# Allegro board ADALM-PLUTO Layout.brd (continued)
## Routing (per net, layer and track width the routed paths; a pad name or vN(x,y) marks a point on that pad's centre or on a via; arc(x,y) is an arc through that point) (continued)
UNNAMED_7_CAP_I147_N1: length 1.3
  TOP w0.102: C205.1 11.29,15.07 R100.1
UNNAMED_7_CAP_I149_N1: length 1.6
  BOTTOM w0.102: Y3.3 14,12.16
  BOTTOM w0.127: 14,12.16 arc(14.01,12.2) C204.1
UNNAMED_7_CNBNC3P_I43_CNTR: length 14.7
  TOP w0.127: D3.2 27.23,47.42
  TOP w0.483: T2.3 38.5,45.27 arc(38.49,45.58) 38.45,45.88 arc(38.45,45.91) 38.44,45.95 arc(38.18,46.48) 37.78,46.93 arc(37.14,47.29) 36.42,47.42 RX2A.1
UNNAMED_7_CNBNC3P_I74_CNTR: length 15.7
  TOP w0.127: D10.2 27.13,19.28
  TOP w0.483: T3.3 39.4,23.29 39.46,22.91 arc(39.07,21.57) 37.8,21 34.06,21 arc(32.36,20.78) 30.77,20.14 arc(29.18,19.49) 27.47,19.28 TX2A.1
UNNAMED_7_CNBNC3P_I125_CNTR: length 9.5
  TOP w0.102: CLK_OUT.1 7.73,10.72 arc(7.74,10.73) D8.2 7.74,14.37 arc(7.79,14.61) 7.92,14.81 arc(8.2,14.99) 8.54,15.06 R100.2 10.34,13.7 arc(10.33,13.67) R98.2
UNNAMED_7_CNBNC5P_I64_CNTR: length 17.8
  TOP w0.305: D4.2 6.32,46.41 6.3,46.39
  TOP w0.483: RX1A.1 8.73,46.39 arc(9.67,46.27) 10.55,45.9 T1.3
UNNAMED_7_CNBNC5P_I83_CNTR: length 18
  TOP w0.305: 6.3,22.95 6.28,22.96 D9.2
  TOP w0.483: TX1A.1 7.11,22.95 arc(9.44,23.91) 10.41,26.24 10.41,28.47 arc(10.75,29.88) 11.71,30.98 arc(12.25,31.28) 12.85,31.47 arc(13.16,31.52) 13.48,31.54 T5.3
UNNAMED_7_ICLTC6957V3_I120_IN: length 2.2
  TOP w0.102: U17.3 arc(18.62,12.27) R10.2
UNNAMED_7_ICLTC6957V3_I120_OUT1: length 1.9
  TOP w0.102: R86.1 12.91,12.24 arc(13.03,12.22) U17.10
UNNAMED_7_ICLTC6957V3_I120_OUT2: length 2.4
  TOP w0.102: R98.1 11.27,13.63 11.27,13.51 arc(11.31,13.27) 11.45,13.06 arc(11.75,12.85) 12.11,12.77 13,12.77 arc(13.05,12.78) 13.1,12.79 arc(13.12,12.79) U17.9
UNNAMED_7_ICLTC6957V3_I120_SD1: length 14.1
  TOP w0.305: U17.12 14.58,10.84 v1(15.29,10.13) 15.29,8.77 Q3.3 ; U17.7 13.17,14.12 R85.2 12.55,16.11 v1(12.55,16.46)
  L5_SIG w0.305: v1(15.29,10.13) 15.29,13.96 12.8,16.46 v1(12.55,16.46)
UNNAMED_7_RES_I152_N1: length 4
  BOTTOM w0.127: 12.77,6.25 12.83,6.2 R5.2
  BOTTOM w0.305: R67.1 10.55,8.22 Y3.1 12.77,7.55 12.77,6.25
UNNAMED_7_RES_I152_N2: length 5.4
  BOTTOM w0.305: R101.2 7.85,8.84 Q2.3 8.05,8.78 8.48,9.22 10.46,9.22 R67.2
UNNAMED_9_ADP198_I365_VOUT: length 5.2
  TOP w0.254: 101.2,42.75 U16.A2 101.58,42.37
  TOP w0.508: F1.1 101.59,41.83 ; F1.1 101.59,40.61 ; F1.1 101.06,41.22
  TOP w0.635: 100.18,41.16 C172.1 100.87,41.79 ; 98.21,41.79 C171.1 98.91,41.16
UNNAMED_9_ADP2114_I196_FREQ: length 1.6
  TOP w0.305: U6.3 96.09,43.52 R53.2
UNNAMED_9_ADP2114_I196_OPCFG: length 1.8
  TOP w0.305: v1(95.35,44.9) 95.23,45.02 U6.6
  BOTTOM w0.508: v1(95.35,44.9) 94.47,44.9 R54.1
UNNAMED_9_ADP2114_I196_SS1: length 2.1
  TOP w0.203: v2(93.06,40.71) 92.8,41.09 U6.30
  BOTTOM w0.254: C7.2 93.38,40.4 v2(93.06,40.71)
UNNAMED_9_ADP2114_I196_SS2: length 1.9
  TOP w0.203: v2(93.06,47.83) 92.8,47.44 U6.11
  BOTTOM w0.305: v2(93.06,47.83) 93.06,47.3 C139.2
UNNAMED_9_ADP2114_I196_SW1: length 3.7
  TOP w0.305: 88.49,42.54 88.97,43.02 U6.23 ; 89.25,41.98 89.51,42.24 89.51,42.43 U6.24 88.9,42.52
  BOTTOM w0.203: R89.1 v1(87.24,42.4)
UNNAMED_9_ADP2114_I196_SW3: length 2.1
  TOP w0.305: 89.28,46.54 89.48,46.34 89.48,46.13 U6.17 88.9,46.02 ; 88.9,45.52 U6.18
UNNAMED_9_CAP_I163_N1: length 7
  TOP w0.305: 83.84,37.67 C146.1 84.67,38.64
  TOP w0.762: 82.71,41.22 L3.2 83.7,39.13
  TOP w1.016: 83.12,37.37 L5.1 81.76,38.15
UNNAMED_9_CAP_I214_N2: length 1
  BOTTOM w0.508: R60.2 C147.2
UNNAMED_9_CAP_I224_N2: length 1
  TOP w0.305: R61.2 C144.2
UNNAMED_9_CAP_I358_N2: length 5.4
  TOP w0.305: 106.91,40.52 C177.2 ; C177.2 106.21,41.16 ; C177.2 107.61,41.16
  TOP w0.508: R55.1 105.72,30.51 106.14,30.93
  TOP w0.635: 107.69,39.61 P2.SH3 106.48,38.84
UNNAMED_9_CAP_I377_N2: length 4.5
  TOP w0.508: C181.2 104.62,48.71
  TOP w0.762: 106.48,48.27 P3.SH1 107.69,47.51 ; 106.14,47.32 R58.1 105.47,48.22
UNNAMED_9_CAP_I446_N1: length 5.4
  TOP w0.305: D2.5 102.46,53.99
  TOP w0.406: 103.65,53.75 P3.1
  TOP w0.508: 97.06,55.43 E11.2 97.91,56.41 ; 100.18,54.43 C214.1 99.32,53.63
UNNAMED_9_CAP_I447_N1: length 7.1
  TOP w0.508: 95.36,55.43 E11.1 94.51,56.41
  TOP w0.635: C213.1 92.65,53.63 ; C213.1 90.94,53.63 ; C213.1 91.79,54.43 ; E9.2 92.77,55.48 ; E9.2 91.79,54.63 ; E9.2 90.82,55.48
UNNAMED_9_CHOKE4P_I350_N2: length 7.1
  TOP w0.102: 101.95,34.49 101.59,34.86 99.49,34.86 99.23,34.6 L6.2 ; 101.95,34.49 102.32,34.86 104.13,34.86 104.24,34.74 104.94,34.74 P2.3 ; 101.95,34.49 D1.1
UNNAMED_9_CHOKE4P_I350_N3: length 7.1
  TOP w0.102: 101.95,35.51 101.95,35.51 101.57,35.13 99.51,35.13 99.23,35.4 L6.3 ; 101.95,35.51 102.34,35.13 104.11,35.13 104.24,35.25 104.95,35.25 P2.2 ; 101.95,35.51 D1.6
UNNAMED_9_CN5P3SHLD_I359_N1: length 6.4
  TOP w0.305: 101.48,37.32 E3.2 ; E3.2 D1.5 ; E3.2 103.44,37.32 ; 100.39,36.56 C211.1 101.19,37.41
  TOP w0.406: 103.81,35.97 P2.1
UNNAMED_9_CN5P3SHLD_I378_N4: length 2.2
  TOP w0.127: D2.3 102.97,52.02 103.22,51.76 104.98,51.76 P3.4
UNNAMED_9_LINLTC4415_I386_CLIM1: length 4.1
  TOP w0.127: U8.4 91.29,60.3 v1(91.28,60.29)
  BOTTOM w0.127: R78.2 91.16,61.41 91.28,61.29 v1(91.28,60.29)
UNNAMED_9_LINLTC4415_I386_CLIM2: length 5.1
  TOP w0.127: U8.5 91.79,59.91 v1(91.79,59.91)
  BOTTOM w0.127: v1(91.79,59.91) 91.79,60.65 92.56,61.41 R73.1
UNNAMED_11_741G126_I97_Y: length 3.3
  BOTTOM w0.254: U10.4 59.77,64.38 R94.2 R95.1
UNNAMED_11_CAP_I83_N1: length 5.2
  BOTTOM w0.254: U9.9 67.6,59.64 C187.1 70.24,58.05 R92.1 70.34,57.97 R80.2
UNNAMED_11_CAP_I92_N1: length 2
  BOTTOM w0.254: C189.1 69.44,59.51 68.38,60.57 U9.8
UNNAMED_11_ICFT230XQ_I103_USBDM: length 1.8
  BOTTOM w0.102: U9.7 69.41,61.22 R79.2
UNNAMED_11_ICFT230XQ_I103_USBDP: length 1.9
  BOTTOM w0.102: R81.2 69.28,61.87 U9.6
UNNAMED_11_ICUSB3320C_I29_RBIAS: length 1.6
  TOP w0.127: v1(79,28.32) U15.24
  BOTTOM w0.127: R77.1 79,27.81 v1(79,28.32)
UNNAMED_11_ICUSB3320C_I29_REFCL: length 2.2
  TOP w0.254: U15.26 77.8,29.4 R82.1
UNNAMED_11_RES_I67_N2: length 1.5
  TOP w0.305: R82.2 78.46,32.47 Y1.3
USB_FS_SLEEP: length 3.6
  BOTTOM w0.254: U10.1 62.05,61.29 R93.1 63.05,61.22 U9.14
USB_ID: length 31.8
  TOP w0.127: U15.23 80.19,26.98 81.77,28.56 v1(81.77,29.07) ; D1.3 103.25,34.02 v1(103.87,34.02) P2.4
  L5_SIG w0.127: v1(103.87,34.02) 103.11,34.78 93.2,34.78 92.44,34.02 92.44,32.5 89.65,29.7 82.41,29.7 v1(81.77,29.07)
USB_OTG_CPEN: length 41
  TOP w0.127: U15.17 79,23.33 79.36,22.97 v1(80.76,22.97) ; v1(101.7,44.52) 102.08,44.15 U16.B1
  L5_SIG w0.127: v1(101.7,44.52) 101.66,44.56 100.09,44.56 96.49,40.97 96.49,36.97 94.69,35.16 93.05,35.16 92.06,34.18 92.06,32.65 89.49,30.08 81.52,30.08 81.01,29.58 81.01,28.56 81.27,28.31 81.27,24.75 80.76,24.24 v1(80.76,22.97)
USB_OTG_N: length 26.2
  TOP w0.102: L6.4 96.39,35.4 96.11,35.13 95.58,35.13 95.24,34.78 95.24,28.23 94.4,27.39 85.58,27.39 83.06,24.86 79.42,24.86 79.31,24.98 U15.19
USB_OTG_P: length 26.1
  TOP w0.102: L6.1 96.39,34.6 96.18,34.81 95.64,34.81 95.5,34.67 95.5,28.12 94.51,27.12 85.69,27.12 83.17,24.6 79.41,24.6 79.29,24.48 U15.18
USB_UART_N: length 40.4
  TOP w0.102: P3.2 104.16,53.1 103.97,52.91 102.33,52.91 101.95,53.29 ; 101.95,53.29 D2.6 ; 101.95,53.29 101.7,53.03 101.45,53.03 v1(101.32,53.16)
  L5_SIG w0.102: v1(101.32,53.16) 100.92,53.16 100.67,52.91 97.12,52.91 94.33,55.7 85.32,55.7 81.13,59.89 74.78,59.89 73.38,61.29 73.38,61.9 v1(73.65,62.17)
  BOTTOM w0.102: R79.1 71.14,60.91 71.14,60.91 71.85,60.91 ; v1(73.65,62.17) 73.38,61.9 73.38,61.61 73.1,61.32 72.27,61.32 71.85,60.91 ; 71.85,60.91 C196.2
USB_UART_P: length 41
  TOP w0.102: 101.95,52.27 101.7,52.52 101.45,52.52 v1(101.32,52.4) ; 101.95,52.27 D2.1 ; 101.95,52.27 102.32,52.64 103.97,52.64 104.16,52.45 P3.3
  L5_SIG w0.102: v1(72.84,62.17) 73.11,61.9 73.11,61.18 74.67,59.62 81.02,59.62 85.21,55.43 94.22,55.43 97.01,52.65 100.67,52.65 100.92,52.4 v1(101.32,52.4)
  BOTTOM w0.102: C197.2 72.08,62.09 72.08,62.08 ; v1(72.84,62.17) 73.11,61.9 73.11,61.72 72.99,61.59 72.31,61.59 72.08,61.83 72.08,62.08 ; 72.08,62.08 71.85,62.3 R81.1
USB_UART_TX: length 4.7
  BOTTOM w0.254: U10.2 60.42,61.92 60.7,62.2 R107.2 62.92,61.87 U9.15
USB_VBUS_OTG: length 30.3
  TOP w0.254: v1(82.92,29.07) 80.5,26.65 79.74,26.65 79.57,26.48 U15.22
  L5_SIG w0.508: v1(82.92,29.07) 89.9,29.07 93.19,32.36 v1(93.19,33.64) v1(93.83,33.64)
  BOTTOM w0.508: R88.2 100.56,40.21 98.52,38.17 96.37,38.17 93.83,35.63 v1(93.83,33.64) v1(93.19,33.64)
USR_BTN: length 67.2
  TOP w0.127: U4.B9 59.53,32.15 63.33,32.15 63.83,31.65 68.94,31.65 70.25,30.34 70.6,30.34 70.98,30.72 70.98,31.27 71.23,31.53 73.31,31.53 75.04,33.26 75.04,35.42 77.71,38.08 v1(79.49,38.08)
  TOP w0.203: v1(105.81,22.68) S1.1
  L6_SIG w0.127: v1(79.49,38.08) 82.48,38.08 85.82,34.74 85.82,28.27 89.38,24.71 89.38,23.19 89.76,22.81 90.65,22.81 92.17,21.28 100.18,21.28 100.68,21.79 104.92,21.79 v1(105.81,22.68)
  BOTTOM w0.203: v1(79.49,38.08) 79.87,37.7 R57.2
USR_LED: length 57.8
  TOP w0.102: U4.D10 v2(57.93,31.35)
  TOP w0.127: v1(100.68,12.98) R75.1 103.15,12.98 Q4.1
  L6_SIG w0.127: v1(100.68,12.98) 90.57,12.98 85.44,18.11 85.44,22.73 78.73,29.45 78.34,29.45 76.44,31.35 74.15,31.35 72.75,29.94 70.04,29.94 69.54,30.44 68.74,30.44 67.84,31.35 67.84,31.35 59.34,31.35 58.93,30.94 58.33,30.94 v2(57.93,31.35)
VTT_0P75: length 31.4
  TOP w0.203: v1(42.63,52.97) C79.1 41.96,54.23 41.6,54.58 U14.3
  BOTTOM w0.305: 48.92,46.84 R19.2 ; R19.2 48.46,47.25 ; R19.2 49.37,47.25 ; C101.1 44.97,57.6 ; C101.1 44.41,58.16 ; C101.1 44.41,57.05 ; R35.2 52.72,57.5 ; R35.2 R39.2 ; R35.2 R16.2 ; 46.19,50.27 R18.2 ; R18.2 R27.2 ; R18.2 46.6,50.27 R29.2 ; 49.96,47.25 R28.2 ; R28.2 50.42,46.84 ; R28.2 R30.2 ; R29.2 46.19,51.07 ; R29.2 R22.2 ; 46.19,49.47 R27.2 ; R27.2 46.6,49.01 ; 46.5,53.61 R34.2 ; R34.2 R17.2 ; R34.2 46.09,54.07 ; R31.2 R37.2 51.49,53.27 ; 46.6,47.81 R20.2 ; R20.2 46.6,48.73 ; R20.2 46.19,48.27 ; R39.2 R33.2 ; R39.2 53.52,57.5 ; R33.2 54.32,57.5 ; R33.2 54.78,57.09 ; 46.09,54.88 R17.2 ; R17.2 R26.2 46.09,55.68 ; 51.22,46.84 R30.2 ; R30.2 R21.2 ; R16.2 51.92,57.5 ; R16.2 R23.2 ; 42.25,54.38 R43.1 42.81,54.94 ; R23.2 51.12,57.5 ; R23.2 R24.2 50.32,57.5 ; R22.2 46.6,52.33 ; R22.2 46.19,51.87 ; R38.2 R21.2 ; R21.2 52.02,46.84 ; 51.49,52.47 R32.2 ; 51.49,51.67 R36.2 ; R25.2 48.12,57.5
VTTVREF: length 69.4
  TOP w0.152: 52.02,51.17 v2(52.02,50.27)
  TOP w0.305: U2.M8 v2(52.02,50.27) ; 44.13,58.48 44.24,58.48 C81.1 ; 44.13,58.48 U14.6 ; 44.13,58.48 arc(44.19,58.46) 44.25,58.43 arc(44.24,58.44) 44.23,58.46 C84.1 ; U2.H1 v2(55.22,55.87) ; U4.F4 v2(56.33,36.95)
  TOP w0.508: v2(55.22,55.87) v1(55.22,58.62) 54.58,58.62 53.69,57.73 49.25,57.73 48.36,58.62 45.82,58.62 ; 45.82,58.62 44.44,58.62 44.25,58.43 ; 45.82,58.62 45.82,53.77 46.92,52.67 51.12,52.67 52.02,51.77 52.02,51.17
  BOTTOM w0.152: v2(56.33,36.95) 56.72,37.34 56.72,38.16 56.32,38.56 55.92,38.16 55.92,37.36 56.33,36.96 v2(56.33,36.95)
  BOTTOM w0.305: C102.1 52.5,49.78 v2(52.02,50.27) ; v2(55.22,55.87) 55.71,55.87 C63.2 ; 57.92,40.26 C99.2
  BOTTOM w0.508: 56.32,38.56 56.52,38.76 56.52,39.66 57.12,40.26 57.92,40.26 57.92,40.37 63.33,45.78 63.33,56.78 62.53,57.58 57.53,57.58 56.49,58.62 v1(55.22,58.62)

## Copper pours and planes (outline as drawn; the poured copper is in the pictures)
1V8 on TOP (solid shape): 38.61,10.59 38.8,10.59 38.9,10.54 39.01,10.53 39.69,10.53 39.74,10.53 39.79,10.54 39.85,10.54 39.85,10.49 39.91,10.49 39.91,10.43 39.89,10.38 39.89,10.33 39.89,9.64 39.9,9.56 39.93,9.48 39.93,9.22 41.76,9.22 41.76,8.94 41.72,8.91 41.68,8.86 41.41,8.86 41.27,8.8 41.21,8.66 41.21,8.25 41.27,8.11 41.41,8.05 41.68,8.05 41.72,8.01 41.76,7.97 41.76,6.68 39.34,6.68 37.56,8.46 37.56,11.38 38.61,11.38
1V8 on TOP: 84.94,36.52 81.13,36.52 81.13,30.68 85.44,30.68 85.44,36.01
1V8 on TOP: 40.13,55.7 40.13,54.02 40.03,53.92 34.69,53.92 34.69,56.46 38.58,56.46 39.36,55.69 40.12,55.69
1V8 on TOP: 34.64,13.03 31.34,13.03 31.34,11.5 31.85,11 31.85,9.09 34.64,9.09
1V8 on BOTTOM: 24.99,58.62 24.99,56.21 26.13,56.21 26.26,56.08 26.26,54.18 29.94,54.18 29.94,57.6 28.93,57.6 27.91,58.62
1V8 on BOTTOM: 66.27,26.87 63.6,26.87 63.6,33.09 66.27,33.09
1V8 on BOTTOM: 82.66,30.68 85.19,30.68 85.19,35.38 82.66,35.38
1V8 on L8_PWR: 48.48,63.06 52.28,59.26 56.08,63.06 56.08,68.7 66.96,68.46 77.82,67.88 77.82,56.46 44.55,56.46 43.53,57.48 43.53,60.4 37.82,60.4 37.06,59.64 37.06,56.97 37.18,56.84 39.15,56.84 39.15,51.25 40.35,50.05 84.36,50.05 84.36,16.01 98.27,16.01 98.27,5.22 59.6,5.22 59.6,11.31 54.14,11.31 54.14,13.73 50.84,13.73 50.84,11.31 47.85,11.31 42.77,6.23 31.15,6.23 31.15,14.11 36.74,14.11 36.74,23.69 43.47,30.42 43.47,41.35 34.83,49.99 34.83,54.11 26.33,54.11 26.33,56.14 31.6,56.14 31.6,67.98 40.03,68.42 48.48,68.66
1V35 on TOP: 55.73,41.96 55.73,44.17 58.32,44.17 58.32,41.96
1V35 on TOP: 81.25,45.29 81.25,52.14 80.36,53.03 80.36,55.83 84.43,55.83 84.43,45.29
1V35 on TOP: 67.54,52.78 63.73,52.78 63.73,55.32 67.54,55.32
1V35 on L3_PWR: 38.64,52.21 38.64,59.57 50.82,59.55 52.27,59.26 53.73,59.55 77.13,59.51 77.13,56.33 83.48,56.33 83.48,41.09 78.4,41.09 78.4,35.38 57.57,35.38 55.67,37.28 51.09,37.28 51.09,33.79 46.33,33.79 45.12,35 45.12,48.72 41.63,52.21
GND on TOP: 48.48,63.06 52.28,59.26 56.08,63.06 56.08,68.7 80.14,67.71 104.08,65.04 104.95,64.9 107.49,63.47 108.5,60.73 108.5,57.47 108.5,55.88 107.56,55.88 106.81,55.57 106.5,54.82 106.81,54.07 107.56,53.76 108.5,53.76 108.5,51.13 107.56,51.13 106.81,50.82 106.5,50.07 106.81,49.32 107.56,49.01 108.5,49.01 108.5,38.1 107.56,38.1 106.81,37.79 106.5,37.04 106.81,36.29 107.56,35.98 108.5,35.98 108.5,33.35 107.56,33.35 106.81,33.04 106.5,32.29 106.81,31.54 107.56,31.23 108.5,31.23 108.5,29.65 108.5,10.07 108.5,8.6 107.49,5.87 104.95,4.43 104.08,4.29 80.14,1.63 56.08,0.64 56.08,6.28 52.28,10.07 48.48,6.28 48.48,0.68 24.49,1.9 0.64,4.78 0.64,21.69 3.55,21.69 3.63,21.77 3.63,24.2 0.64,24.2 0.64,45.13 3.4,45.13 3.27,45.26 3.27,47.65 0.64,47.65 0.64,64.55 24.49,67.44 48.48,68.66 ; 15 cut-outs
GND on L3_PWR: 0.64,64.55 24.49,67.44 48.48,68.66 48.48,63.06 48.82,61.48 49.79,60.19 38.01,60.21 38.01,52.21 23.4,52.21 23.4,43.63 30.64,36.39 30.64,23.82 32.04,22.42 32.04,9.41 15.78,9.41 15.78,2.75 8.2,3.68 0.64,4.78
GND on L5_SIG: 56.08,68.7 77.28,67.91 98.4,65.83 98.4,64.21 94.59,64.21 94.59,58.8 94.28,58.8 93.93,58.44 93.93,52.45 94.03,52.35 98.4,52.35 98.4,41.09 97.13,39.82 97.13,38.86 97.13,36.33 97.13,36.33 102.21,36.33 102.53,36.01 102.53,29.35 108.48,29.35 108.48,26.92 108.5,26.92 108.5,15.52 108.5,10.08 108.5,8.6 107.49,5.87 104.95,4.43 104.08,4.29 81.55,1.74 58.9,0.67 57.49,0.65 56.08,0.64 56.08,6.28 52.28,10.07 48.48,6.28 48.48,0.68 40.48,0.9 32.48,1.3 32.48,1.3 19.89,2.32 7.34,3.8 3.99,4.28 0.64,4.78 0.64,64.55 1.7,64.72 1.7,64.72 16.68,66.68 31.72,67.98 31.72,67.98 48.48,67.98 48.48,67.13 48.48,63.06 52.28,59.26 56.08,63.06 56.08,67.13 ; 1 cut-out
GND on L8_PWR: 20.23,40.52 35.22,40.52 35.22,23.51 36.1,23.51 36.1,22.3 30.08,28.33 27.34,28.33 27.34,21.85 20.23,21.85
GND on L8_PWR: 108.5,27.38 108.5,8.61 107.49,5.87 104.95,4.43 104.08,4.29 80.14,1.63 56.08,0.64 56.08,6.28 55.56,8.2 54.14,9.59 54.14,10.68 58.96,10.68 58.96,4.58 98.33,4.58 98.33,16.65 85,16.65 85,27.38
GND on L8_PWR: 0.64,64.55 24.49,67.44 48.48,68.66 48.48,63.06 48.66,61.91 49.17,60.87 34.2,60.84 34.2,59.83 10.83,59.83 10.83,19.44 9.49,19.44 8.29,18.24 8.29,9.03 21.63,9.03 21.63,14.11 24.04,14.11 24.04,1.93 12.31,3.16 0.64,4.78
PGND on TOP: 98.4,50.11 98.52,49.98 98.52,47.44 102.46,47.44 102.72,47.19 102.72,46.3 103.22,46.3 103.22,50.75 104.87,50.75 104.87,52.4 96.24,52.4 96.11,52.27 96.11,50.11
PGND on L2_GND, L9_GND: 105.26,55.32 98.02,55.32 97.76,55.57 97.76,56.97 96.11,56.97 96.11,50.11 98.4,50.11 98.52,49.98 98.52,47.44 102.46,47.44 102.72,47.19 102.72,46.3 104.37,46.3 104.37,48.08 103.22,48.08 103.22,49.73 104.62,49.73 105.76,50.87 105.76,54.81
VCCPINT on TOP: 56.03,21.74 64.18,21.74 64.18,24.09 56.03,24.09
VCCPINT on TOP: 76.81,13.03 86.84,13.03 86.84,18.23 76.81,18.23
VCCPINT on L3_PWR: 51.73,36.65 55.4,36.65 57.31,34.74 78.4,34.74 78.4,23.95 83.79,23.95 83.79,15.06 68.55,15.06 68.55,17.92 51.09,17.92 51.09,33.16 51.73,33.16
VDD_INTERFACE on TOP: 31.98,13.66 31.98,17.22 32.1,17.35 32.1,17.97 34.64,17.97 34.64,13.66
VDD_INTERFACE on L8_PWR: 27.98,27.7 29.81,27.7 36.1,21.41 36.1,14.74 27.98,14.74
VIN on TOP: 92.05,39.95 92.05,35.76 89.89,35.76 89.89,40.21 89.38,40.71 89.38,41.35 90.4,42.36 91.41,42.36 91.41,40.59 ; 1 cut-out
VIN on TOP: 50.52,11.5 53.31,11.5 53.31,14.04 50.77,14.04 50.52,13.79
VIN on TOP: 93.7,63.45 82.78,63.45 82.78,65.73 90.4,65.73 91.16,64.97 93.83,64.97 93.83,63.57
VIN on TOP: 90.78,15.95 90.78,17.47 90.65,17.6 90.65,17.9 91.03,17.9 91.08,17.96 91.08,18.36 90.88,18.36 90.65,18.13 90.65,19.12 91.29,19.12 91.29,19.76 94.08,19.76 95.6,18.23 95.6,15.95 ; 1 cut-out
VIN on TOP: 91.92,46.24 90.33,46.24 89.51,47.06 89.51,51.76 91.92,51.76 ; 1 cut-out
VIN on BOTTOM: 27.79,14.68 27.79,13.54 27.66,13.41 27.4,13.41 27.4,11.88 29.94,11.88 29.94,14.42 29.69,14.68
VIN on L3_PWR: 77.76,56.97 77.76,67.88 88.09,67.01 98.39,65.83 98.33,41.23 97.06,39.96 97.06,29.35 108.5,29.35 108.5,8.61 107.49,5.87 104.95,4.43 104.08,4.29 80.14,1.63 56.08,0.64 56.08,6.28 54.5,9.35 51.09,9.89 51.09,17.28 67.92,17.28 67.92,14.42 84.43,14.42 84.43,24.58 79.03,24.58 79.03,40.46 84.11,40.46 84.11,56.97
VIN on L8_PWR: 24.67,14.11 30.52,14.11 30.52,5.6 43.03,5.6 48.11,10.68 51.47,10.68 51.47,13.09 53.5,13.09 53.5,9.87 50.07,9.37 48.48,6.28 48.48,0.68 36.57,1.07 24.67,1.88
VIN on L8_PWR: 62.03,60.27 82.4,60.31 82.4,65.73 88.87,65.73 88.87,57.92 84.36,57.92 84.36,50.68 40.62,50.68 39.79,51.51 39.79,57.1 38.33,57.1 37.82,57.6 37.82,59.13 38.2,59.51 46.2,59.51 46.2,56.72 62.08,56.72 62.08,60.27
VIN_5V_USB_DATA on TOP: 92.56,61.41 99.29,61.41 99.29,59.76 92.68,59.76 92.56,59.89
VIN_5V_USB_DATA on TOP: 104.75,38.3 104.75,41.73 102.21,41.73 102.21,39.95 101.45,39.95 101.45,38.3
VIN_5V_USB_DATA on L3_PWR: 93.06,65.75 99.02,65.75 101.55,65.4 104.08,65.04 104.95,64.9 107.49,63.47 108.5,60.73 108.5,57.47 108.5,55.88 107.56,55.88 106.81,55.57 106.5,54.82 106.81,54.07 107.56,53.76 108.5,53.76 108.5,51.13 107.56,51.13 106.81,50.82 106.5,50.07 106.81,49.32 107.56,49.01 108.5,49.01 108.5,38.1 107.56,38.1 106.81,37.79 106.5,37.04 106.81,36.29 107.56,35.98 108.5,35.98 108.5,33.35 107.56,33.35 106.81,33.04 106.5,32.29 106.81,31.54 107.56,31.23 108.5,31.23 108.5,29.98 97.7,29.98 97.7,37.92 94.08,37.92 93.06,38.94
VIN_5V_USB_POWER on TOP: 88.87,56.46 88.87,61.54 90.65,61.54 90.65,60.27 92.56,60.27 92.56,59.13 93.32,59.13 93.32,56.46
VIN_5V_USB_POWER on TOP: 104.24,43.76 104.75,43.76 104.75,45.67 102.46,45.67 102.46,43 101.95,43 101.95,42.11 104.24,42.11
VIN_5V_USB_POWER on L8_PWR: 87.09,60.91 94.46,60.91 94.46,57.6 108.5,57.6 108.5,55.88 107.56,55.88 106.81,55.57 106.5,54.82 106.81,54.07 107.56,53.76 108.5,53.76 108.5,51.13 107.56,51.13 106.81,50.82 106.5,50.07 106.81,49.32 107.56,49.01 108.5,49.01 108.5,38.1 107.56,38.1 106.81,37.79 106.5,37.04 106.81,36.29 107.56,35.98 108.5,35.98 108.5,33.35 107.56,33.35 106.81,33.04 106.5,32.29 106.81,31.54 107.56,31.23 108.5,31.23 108.5,27.63 84.55,27.63 84.43,27.76 84.43,58.24
(no net) on TOP: 37.56,12.01 37.56,16.33 42.14,16.33 42.52,16.71 43.79,16.71 43.79,15.19 42.14,15.19 41.88,14.93 41.88,14.55 39.98,14.55 39.98,14.35 41.88,14.35 41.88,13.41 41.76,13.28 39.85,13.28 39.85,12.01 38.91,12.01 38.91,13.18 38.61,13.18 38.61,12.01
(no net) on TOP: 39.34,6.68 37.56,8.46 37.56,11.76 39.85,11.76 39.85,10.49 41.76,10.49 41.76,9.62 39.93,9.62 39.93,9.22 41.76,9.22 41.76,6.68 ; 1 cut-out
1P3_SUPPLY_A on TOP (solid shape): outline of 84 points within 37.56,12.01 43.79,16.48
1P3_SUPPLY_A on L3_PWR: 24.04,51.57 41.37,51.57 44.49,48.46 44.49,34.74 46.07,33.16 50.46,33.16 50.46,17.92 46.58,17.92 38.07,9.41 32.68,9.41 32.68,22.68 31.28,24.08 31.28,36.65 24.04,43.89
1P3_SUPPLY_B on BOTTOM: 21.44,59.51 24.36,59.51 24.36,57.73 24.23,57.6 24.99,57.6 24.99,56.33 24.86,56.21 23.59,56.21 23.59,49.17 23.26,48.84 20.67,48.84 20.55,48.97 20.55,52.91 20.93,53.29 20.93,59
1P3_SUPPLY_B on L8_PWR: 11.47,59.19 34.2,59.19 34.2,56.78 25.69,56.78 25.69,53.48 34.2,53.48 34.2,49.73 42.84,41.09 42.84,30.69 36.29,24.14 35.85,24.14 35.85,41.16 19.59,41.16 19.59,21.22 27.34,21.22 27.34,14.74 20.86,14.74 20.86,19.44 11.47,19.44
1P8V_CLK on TOP: 44.55,15.19 47.22,15.19 47.47,15.44 48.49,15.44 48.49,16.33 47.98,16.84 44.55,16.84
1P8V_CLK on L3_PWR: 46.84,17.28 50.46,17.28 50.46,9.61 49.01,8.21 48.48,6.28 48.48,0.68 32.43,1.31 16.42,2.68 16.42,7.57 6.2,7.57 5.81,7.95 5.81,13.28 7.47,13.28 7.47,8.96 7.59,8.84 10.26,8.84 10.32,8.77 38.33,8.77
3P3V_CLK on TOP: 14.07,18.62 16.1,18.62 16.31,18.41 16.31,15.11 16.61,14.81 18.39,14.81 18.39,13.92 15.31,13.92 14.83,14.4 14.83,14.55 14.68,14.7 13.66,14.7 13.61,14.75 13.61,16.18 13.46,16.33 13.26,16.33 13.16,16.43 13.16,17.14 13.26,17.24 13.84,17.24 14.07,17.47
3P3V_CLK on L8_PWR: 9.76,18.81 20.23,18.81 20.23,14.11 20.99,14.11 20.99,9.66 8.93,9.66 8.93,17.98
SYNC on TOP: 87.48,13.03 90.27,13.03 90.27,19.12 88.24,19.12 87.48,18.36 ; 1 cut-out
TX1A_N on TOP (solid shape): 22.51,30.06 22.72,29.91 22.98,29.85 23.1,29.85 23.1,29 21.09,29 20.48,29.61 20.48,30.06
TX1A_P on TOP (solid shape): 23.1,30.69 22.77,30.69 22.55,30.47 20.48,30.47 20.48,30.93 21.09,31.54 23.1,31.54
UNNAMED_2_ADM7160V2_I254_VIN on TOP: 50.26,15.57 51.03,15.57 51.53,15.06 53.31,15.06 53.31,17.85 50.52,17.85 50.52,16.71 50.26,16.46
UNNAMED_2_ADP2164_I29_EN on TOP: 91.29,20.01 94.46,20.01 94.46,21.16 91.29,21.16 ; 1 cut-out
UNNAMED_9_ADP198_I365_VOUT on TOP: 101.06,42.87 101.06,42.36 98.14,42.36 98.14,40.33 101.83,40.33 101.83,42.87
UNNAMED_9_ADP2114_I196_SW1 on TOP: 90.08,43.13 90.08,42.56 88.36,40.84 85.44,40.84 85.44,43.13 ; 1 cut-out
UNNAMED_9_ADP2114_I196_SW3 on TOP: 85.44,45.29 85.44,49.1 86.84,49.1 86.84,47.57 88.45,47.57 89.78,46.24 90.08,46.24 90.08,45.29 89.44,45.29 89.44,46.34 88.93,46.34 88.93,45.29
UNNAMED_9_CAP_I163_N1 on TOP: 81.25,36.9 85.06,36.9 85.06,39.06 84.55,39.06 84.3,39.32 84.3,43.13 81.25,43.13
UNNAMED_9_CAP_I358_N2 on TOP: 105.51,29.98 105.51,32.46 106.02,32.97 106.02,36.52 105.76,36.78 105.76,41.54 108.5,41.54 108.5,38.1 107.56,38.1 106.81,37.79 106.5,37.04 106.81,36.29 107.56,35.98 108.5,35.98 108.5,33.35 107.56,33.35 106.81,33.04 106.5,32.29 106.81,31.54 107.56,31.23 108.49,31.23 108.49,30.17 108.3,29.98
UNNAMED_9_CAP_I377_N2 on TOP: 105.26,49.6 105.51,49.86 105.51,50.24 106,50.73 106,54.95 105.49,55.46 105.49,57.1 108.5,57.1 108.5,55.88 107.56,55.88 106.81,55.57 106.5,54.82 106.81,54.07 107.56,53.76 108.5,53.76 108.5,51.13 107.56,51.13 106.81,50.82 106.5,50.07 106.81,49.32 107.56,49.01 108.5,49.01 108.5,48.06 108.47,48.06 108.47,46.3 104.62,46.3 104.62,48.08 103.22,48.08 103.22,49.6
UNNAMED_9_CAP_I446_N1 on TOP: 104.87,55.32 104.87,53.29 104.75,53.16 96.24,53.16 96.11,53.29 96.1,56.97 98.09,56.97 98.09,55.32
UNNAMED_9_CAP_I447_N1 on TOP: 95.73,53.16 94.21,53.16 93.95,53.41 90.65,53.41 90.65,56.33 93.95,56.33 93.95,56.97 95.86,56.97 95.86,53.29
UNNAMED_9_CN5P3SHLD_I359_N1 on TOP: 101.45,36.01 101.19,36.27 99.67,36.27 99.67,38.3 104.11,38.3 104.11,36.4 104.24,36.27 105.13,36.27 105.26,36.14 105.26,35.51 101.57,35.51 101.45,35.63
VTT_0P75 on BOTTOM: 44.17,58.62 44.17,55.7 43.66,55.19 42.01,55.19 42.01,52.88 42.61,52.27 44.31,52.27 44.71,51.87 44.71,46.07 52.22,46.07 52.22,47.47 46.72,47.47 46.72,52.02 49.07,52.02 49.7,51.38 52.17,51.38 52.17,53.87 49.92,53.87 49.22,53.17 48.35,53.17 46.82,54.7 46.82,56.08 46.84,56.08 46.84,57.1 49.63,57.1 49.88,56.84 55.09,56.84 55.09,57.86 54.33,58.62 50.39,58.62 49.5,59.51 45.06,59.51

Small or netless copper shapes (teardrops, artwork), in the pictures only: 2 on TOP, 1 on BOTTOM, 1 on L3_PWR, 1 on L5_SIG, 1 on L6_SIG, 1 on L8_PWR

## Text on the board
BOTTOM: SECONDARY SIDE
TOP: PRIMARY SIDE | 08-043758 REV D Z | ADALM-PLUTO
Ref Des/Assembly Top: K | A | ASSEMBLY NOTES: | 1. DS1 AND DS2 ARE RIGHT ANGLE LEDs
Ref Des/Silkscreen Top: 3V3 MAX | 1.8V | LOGIC LEVEL | K | A
DIMENSION: " " | SEE DETAIL A | -0.076 | -0.242 | 2.486 | 2.320 | 2.240 | .004 | 0 | 4.297 | R13.599 | 1.932 | 1.899 | 1.745 | 1.712 | 1.232 | 1.199 | 1.045 | 1.012 | R.191 | 0.0330 | (2PLCS) | 0.0165 | 0.0395 | 0.0790 | RADIUS | FULL | SCALE: NONE | DETAIL A | 0.1870 | EDGE | PCB | REF | ARRAY DIMENSIONS | BOARD DIMENSIONS | x2 | FIDUCIAL | TOOLING HOLE (4X) | MOLEX47590-0001_CUTOUT-DETAIL | DIA MAX | -1.074 | .860 | .984 | 1.109 | 3.223 | 2.730
PAGE_OUTLINE: B | C | D | AS PER ECR-064863 | AS PER ECR-089480 | AS PER ECR-092850 | 22NOV16 | 19AUG19 | 20MAR20 | MBANCISOR | CUSTOMER EVAL BOARD Z
User.15: PREPREG 2.98MILS | PREPREG 2.9MILS | CORE 3MILS | NOTE: ALL IMPEDANCE TOLERANCE +/-10% | LAYER | L1 | L5 | L6 | L10 | SE = SINGLE ENDED, DP = DIFFERENTIAL PAIR | 100 OHMS DP | IMPEDANCE | 50 OHMS SE | 40 OHMS SE | 90 OHMS DP | 80 OHMS DP | REFERENCE | L4,L7 | L2 | L4 | L9 | LINE WIDTH | 19MILS | 6.5MILS | 4MILS | 9MILS | 4.5MILS | 5.5MILS | 5MILS | SPACE | 7MILS | 6MILS | N/A | IMPEDANCE TABLE
User.17: L2 GND | 08-      -07
User.18: L3 PWR | 08-      -08
User.19: L4 GND | 08-      -09
User.20: L5 SIG | 08-      -10
User.22: L6 SIG | 08-      -11
User.23: L7 GND | 08-      -12
User.24: L8 PWR | 08-      -13
User.25: L9 GND | 08-      -14
User.27: L2 GND | 08-      -075
User.28: L3 PWR | 08-      -085
User.29: L4 GND | 08-      -095
User.30: L5 SIG | 08-      -105
User.31: L6 SIG | 08-      -115
User.32: L7 GND | 08-      -125
User.33: L8 PWR | 08-      -135
User.34: L9 GND | 08-      -145
User.45: FIGURE | SIZE | 8.0 | 10.0 | 20.0 | 28.0 | 45.0 | 25.0 | 50.0 | 90.0 | 126.0 | 34.0x26.0 | 51.0x24.0 | DRILL CHART: TOP to BOTTOM | ALL UNITS ARE IN MILS | PLATED | NON-PLATED | QTY | 601 | 883 | 15 | 10 | 24 | 18 | 2 | 12 | 1 | 8 | 4 | TOLERANCE/NOTES
